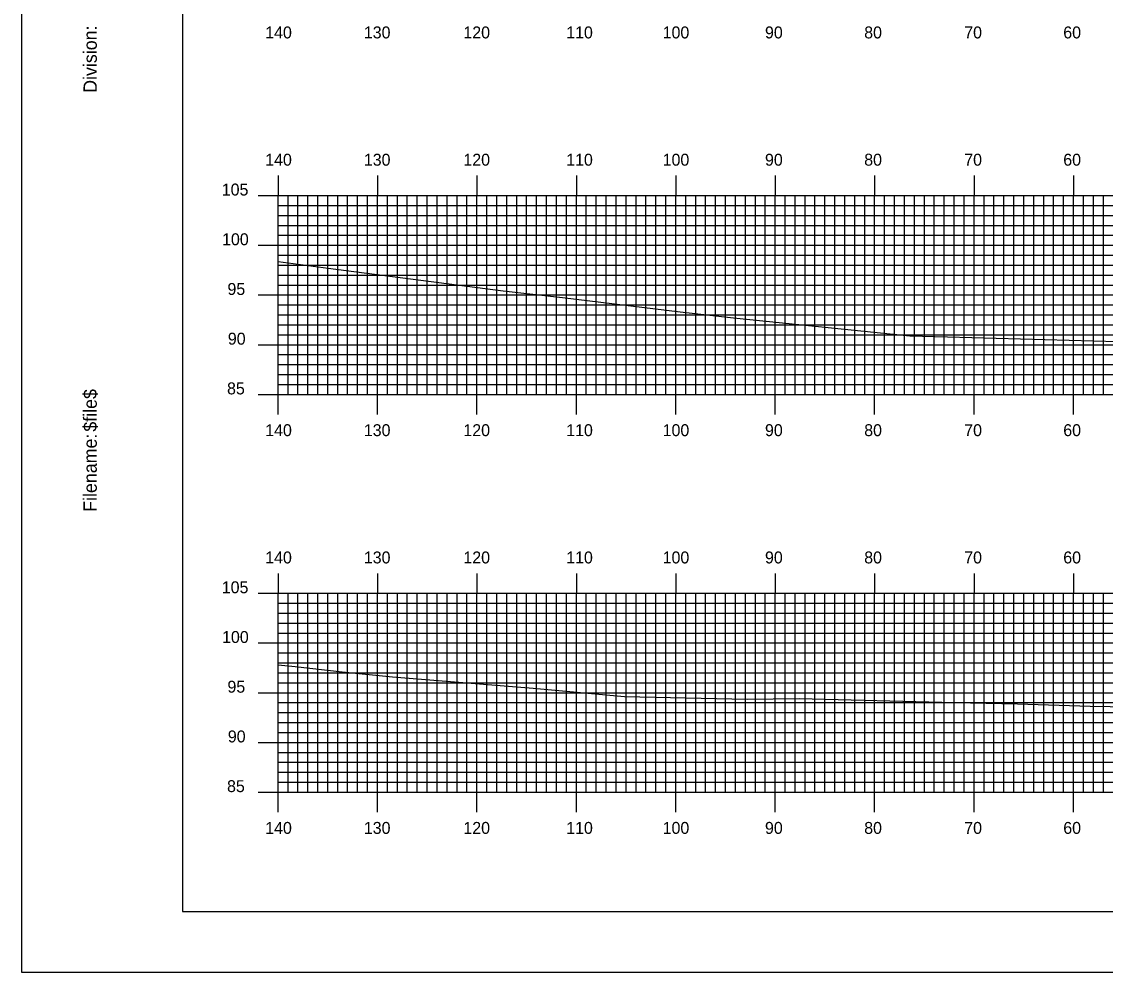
# Model space of a CAD drawing. Extents: x 1775564 to 1775907, y 442591 to 442811.
# Drawn here: x 1775563.9 to 1775672.9, y 442590.5 to 442686.2 of the extents above; entities that cross this region are included whole.
import ezdxf

# ---------------------------------------------------------------- set-up
doc = ezdxf.new("R2010")
doc.units = 0
for name, color, linetype in [('BORDER', 7, 'Continuous'), ('H_V ANNOTATION', 7, 'Continuous'), ('MAJOR', 7, 'Continuous'), ('MINOR', 7, 'Continuous'), ('PLOT BOUNDARY', 7, 'Continuous'), ('S_Roadway_Centerline', 7, 'Continuous')]:
    doc.layers.add(name, color=color, linetype=linetype)

msp = doc.modelspace()

# ---------------------------------------------------------------- linework, layer by layer
at = {"layer": 'BORDER'}
msp.add_lwpolyline([(1775580.11, 442596.67), (1775900.11, 442596.67), (1775900.11, 442806.67), (1775580.11, 442806.67)], close=True, dxfattribs=at)
at = {"layer": 'MAJOR'}
for p, q in [((1775589.71, 442670.67), (1775589.71, 442668.67)), ((1775599.71, 442670.67), (1775599.71, 442668.67)), ((1775609.71, 442670.67), (1775609.71, 442668.67)), ((1775619.71, 442670.67), (1775619.71, 442668.67)), ((1775629.71, 442670.67), (1775629.71, 442668.67)), ((1775639.71, 442670.67), (1775639.71, 442668.67)), ((1775649.71, 442670.67), (1775649.71, 442668.67)), ((1775659.71, 442670.67), (1775659.71, 442668.67)), ((1775669.71, 442670.67), (1775669.71, 442668.67)), ((1775587.71, 442668.67), (1775589.71, 442668.67)), ((1775589.71, 442668.67), (1775869.71, 442668.67)), ((1775589.71, 442648.67), (1775589.71, 442668.67)), ((1775589.71, 442648.67), (1775589.71, 442668.67)), ((1775589.71, 442668.67), (1775869.71, 442668.67)), ((1775599.71, 442648.67), (1775599.71, 442668.67)), ((1775609.71, 442648.67), (1775609.71, 442668.67)), ((1775619.71, 442648.67), (1775619.71, 442668.67)), ((1775629.71, 442648.67), (1775629.71, 442668.67)), ((1775639.71, 442648.67), (1775639.71, 442668.67)), ((1775649.71, 442648.67), (1775649.71, 442668.67)), ((1775659.71, 442648.67), (1775659.71, 442668.67)), ((1775669.71, 442648.67), (1775669.71, 442668.67)), ((1775587.71, 442663.67), (1775589.71, 442663.67)), ((1775589.71, 442663.67), (1775869.71, 442663.67)), ((1775587.71, 442658.67), (1775589.71, 442658.67)), ((1775589.71, 442658.67), (1775869.71, 442658.67)), ((1775587.71, 442653.67), (1775589.71, 442653.67)), ((1775589.71, 442653.67), (1775869.71, 442653.67)), ((1775587.71, 442648.67), (1775589.71, 442648.67)), ((1775589.71, 442648.67), (1775869.71, 442648.67)), ((1775589.71, 442648.67), (1775869.71, 442648.67)), ((1775589.71, 442646.66), (1775589.71, 442648.67)), ((1775599.71, 442646.66), (1775599.71, 442648.67)), ((1775609.71, 442646.66), (1775609.71, 442648.67)), ((1775619.71, 442646.66), (1775619.71, 442648.67)), ((1775629.71, 442646.66), (1775629.71, 442648.67)), ((1775639.71, 442646.66), (1775639.71, 442648.67)), ((1775649.71, 442646.66), (1775649.71, 442648.67)), ((1775659.71, 442646.66), (1775659.71, 442648.67)), ((1775669.71, 442646.66), (1775669.71, 442648.67)), ((1775589.71, 442630.67), (1775589.71, 442628.67)), ((1775599.71, 442630.67), (1775599.71, 442628.67)), ((1775609.71, 442630.67), (1775609.71, 442628.67)), ((1775619.71, 442630.67), (1775619.71, 442628.67)), ((1775629.71, 442630.67), (1775629.71, 442628.67)), ((1775639.71, 442630.67), (1775639.71, 442628.67)), ((1775649.71, 442630.67), (1775649.71, 442628.67)), ((1775659.71, 442630.67), (1775659.71, 442628.67)), ((1775669.71, 442630.67), (1775669.71, 442628.67)), ((1775587.71, 442628.67), (1775589.71, 442628.67)), ((1775589.71, 442628.67), (1775869.71, 442628.67)), ((1775589.71, 442608.67), (1775589.71, 442628.67)), ((1775589.71, 442608.67), (1775589.71, 442628.67)), ((1775589.71, 442628.67), (1775869.71, 442628.67)), ((1775599.71, 442608.67), (1775599.71, 442628.67)), ((1775609.71, 442608.67), (1775609.71, 442628.67)), ((1775619.71, 442608.67), (1775619.71, 442628.67)), ((1775629.71, 442608.67), (1775629.71, 442628.67)), ((1775639.71, 442608.67), (1775639.71, 442628.67)), ((1775649.71, 442608.67), (1775649.71, 442628.67)), ((1775659.71, 442608.67), (1775659.71, 442628.67)), ((1775669.71, 442608.67), (1775669.71, 442628.67)), ((1775587.71, 442623.67), (1775589.71, 442623.67)), ((1775589.71, 442623.67), (1775869.71, 442623.67)), ((1775587.71, 442618.67), (1775589.71, 442618.67)), ((1775589.71, 442618.67), (1775869.71, 442618.67)), ((1775587.71, 442613.67), (1775589.71, 442613.67)), ((1775589.71, 442613.67), (1775869.71, 442613.67)), ((1775587.71, 442608.67), (1775589.71, 442608.67)), ((1775589.71, 442608.67), (1775869.71, 442608.67)), ((1775589.71, 442608.67), (1775869.71, 442608.67)), ((1775589.71, 442606.66), (1775589.71, 442608.67)), ((1775599.71, 442606.66), (1775599.71, 442608.67)), ((1775609.71, 442606.66), (1775609.71, 442608.67)), ((1775619.71, 442606.66), (1775619.71, 442608.67)), ((1775629.71, 442606.66), (1775629.71, 442608.67)), ((1775639.71, 442606.66), (1775639.71, 442608.67)), ((1775649.71, 442606.66), (1775649.71, 442608.67)), ((1775659.71, 442606.66), (1775659.71, 442608.67)), ((1775669.71, 442606.66), (1775669.71, 442608.67))]:
    msp.add_line(p, q, dxfattribs=at)
at = {"layer": 'MINOR'}
for p, q in [((1775590.71, 442648.67), (1775590.71, 442668.67)), ((1775591.71, 442648.67), (1775591.71, 442668.67)), ((1775592.71, 442648.67), (1775592.71, 442668.67)), ((1775593.71, 442648.67), (1775593.71, 442668.67)), ((1775594.71, 442648.67), (1775594.71, 442668.67)), ((1775595.71, 442648.67), (1775595.71, 442668.67)), ((1775596.71, 442648.67), (1775596.71, 442668.67)), ((1775597.71, 442648.67), (1775597.71, 442668.67)), ((1775598.71, 442648.67), (1775598.71, 442668.67)), ((1775600.71, 442648.67), (1775600.71, 442668.67)), ((1775601.71, 442648.67), (1775601.71, 442668.67)), ((1775602.71, 442648.67), (1775602.71, 442668.67)), ((1775603.71, 442648.67), (1775603.71, 442668.67)), ((1775604.71, 442648.67), (1775604.71, 442668.67)), ((1775605.71, 442648.67), (1775605.71, 442668.67)), ((1775606.71, 442648.67), (1775606.71, 442668.67)), ((1775607.71, 442648.67), (1775607.71, 442668.67)), ((1775608.71, 442648.67), (1775608.71, 442668.67)), ((1775610.71, 442648.67), (1775610.71, 442668.67)), ((1775611.71, 442648.67), (1775611.71, 442668.67)), ((1775612.71, 442648.67), (1775612.71, 442668.67)), ((1775613.71, 442648.67), (1775613.71, 442668.67)), ((1775614.71, 442648.67), (1775614.71, 442668.67)), ((1775615.71, 442648.67), (1775615.71, 442668.67)), ((1775616.71, 442648.67), (1775616.71, 442668.67)), ((1775617.71, 442648.67), (1775617.71, 442668.67)), ((1775618.71, 442648.67), (1775618.71, 442668.67)), ((1775620.71, 442648.67), (1775620.71, 442668.67)), ((1775621.71, 442648.67), (1775621.71, 442668.67)), ((1775622.71, 442648.67), (1775622.71, 442668.67)), ((1775623.71, 442648.67), (1775623.71, 442668.67)), ((1775624.71, 442648.67), (1775624.71, 442668.67)), ((1775625.71, 442648.67), (1775625.71, 442668.67)), ((1775626.71, 442648.67), (1775626.71, 442668.67)), ((1775627.71, 442648.67), (1775627.71, 442668.67)), ((1775628.71, 442648.67), (1775628.71, 442668.67)), ((1775630.71, 442648.67), (1775630.71, 442668.67)), ((1775631.71, 442648.67), (1775631.71, 442668.67)), ((1775632.71, 442648.67), (1775632.71, 442668.67)), ((1775633.71, 442648.67), (1775633.71, 442668.67)), ((1775634.71, 442648.67), (1775634.71, 442668.67)), ((1775635.71, 442648.67), (1775635.71, 442668.67)), ((1775636.71, 442648.67), (1775636.71, 442668.67)), ((1775637.71, 442648.67), (1775637.71, 442668.67)), ((1775638.71, 442648.67), (1775638.71, 442668.67)), ((1775640.71, 442648.67), (1775640.71, 442668.67)), ((1775641.71, 442648.67), (1775641.71, 442668.67)), ((1775642.71, 442648.67), (1775642.71, 442668.67)), ((1775643.71, 442648.67), (1775643.71, 442668.67)), ((1775644.71, 442648.67), (1775644.71, 442668.67)), ((1775645.71, 442648.67), (1775645.71, 442668.67)), ((1775646.71, 442648.67), (1775646.71, 442668.67)), ((1775647.71, 442648.67), (1775647.71, 442668.67)), ((1775648.71, 442648.67), (1775648.71, 442668.67)), ((1775650.71, 442648.67), (1775650.71, 442668.67)), ((1775651.71, 442648.67), (1775651.71, 442668.67)), ((1775652.71, 442648.67), (1775652.71, 442668.67)), ((1775653.71, 442648.67), (1775653.71, 442668.67)), ((1775654.71, 442648.67), (1775654.71, 442668.67)), ((1775655.71, 442648.67), (1775655.71, 442668.67)), ((1775656.71, 442648.67), (1775656.71, 442668.67)), ((1775657.71, 442648.67), (1775657.71, 442668.67)), ((1775658.71, 442648.67), (1775658.71, 442668.67)), ((1775660.71, 442648.67), (1775660.71, 442668.67)), ((1775661.71, 442648.67), (1775661.71, 442668.67)), ((1775662.71, 442648.67), (1775662.71, 442668.67)), ((1775663.71, 442648.67), (1775663.71, 442668.67)), ((1775664.71, 442648.67), (1775664.71, 442668.67)), ((1775665.71, 442648.67), (1775665.71, 442668.67)), ((1775666.71, 442648.67), (1775666.71, 442668.67)), ((1775667.71, 442648.67), (1775667.71, 442668.67)), ((1775668.71, 442648.67), (1775668.71, 442668.67)), ((1775670.71, 442648.67), (1775670.71, 442668.67)), ((1775671.71, 442648.67), (1775671.71, 442668.67)), ((1775672.71, 442648.67), (1775672.71, 442668.67)), ((1775589.71, 442667.67), (1775869.71, 442667.67)), ((1775589.71, 442667.67), (1775591.72, 442667.67)), ((1775589.71, 442666.67), (1775869.71, 442666.67)), ((1775589.71, 442666.67), (1775591.72, 442666.67)), ((1775589.71, 442665.67), (1775869.71, 442665.67)), ((1775589.71, 442665.67), (1775591.72, 442665.67)), ((1775589.71, 442664.67), (1775869.71, 442664.67)), ((1775589.71, 442664.67), (1775591.72, 442664.67)), ((1775589.71, 442662.67), (1775869.71, 442662.67)), ((1775589.71, 442662.67), (1775591.72, 442662.67)), ((1775589.71, 442661.67), (1775869.71, 442661.67)), ((1775589.71, 442661.67), (1775591.72, 442661.67)), ((1775589.71, 442660.67), (1775869.71, 442660.67)), ((1775589.71, 442660.67), (1775591.72, 442660.67)), ((1775589.71, 442659.67), (1775869.71, 442659.67)), ((1775589.71, 442659.67), (1775591.72, 442659.67)), ((1775589.71, 442657.67), (1775869.71, 442657.67)), ((1775589.71, 442657.67), (1775591.72, 442657.67)), ((1775589.71, 442656.67), (1775869.71, 442656.67)), ((1775589.71, 442656.67), (1775591.72, 442656.67)), ((1775589.71, 442655.67), (1775869.71, 442655.67)), ((1775589.71, 442655.67), (1775591.72, 442655.67)), ((1775589.71, 442654.67), (1775869.71, 442654.67)), ((1775589.71, 442654.67), (1775591.72, 442654.67)), ((1775589.71, 442652.67), (1775869.71, 442652.67)), ((1775589.71, 442652.67), (1775591.72, 442652.67)), ((1775589.71, 442651.67), (1775869.71, 442651.67)), ((1775589.71, 442651.67), (1775591.72, 442651.67)), ((1775589.71, 442650.67), (1775869.71, 442650.67)), ((1775589.71, 442650.67), (1775591.72, 442650.67)), ((1775589.71, 442649.67), (1775869.71, 442649.67)), ((1775589.71, 442649.67), (1775591.72, 442649.67)), ((1775590.71, 442608.67), (1775590.71, 442628.67)), ((1775591.71, 442608.67), (1775591.71, 442628.67)), ((1775592.71, 442608.67), (1775592.71, 442628.67)), ((1775593.71, 442608.67), (1775593.71, 442628.67)), ((1775594.71, 442608.67), (1775594.71, 442628.67)), ((1775595.71, 442608.67), (1775595.71, 442628.67)), ((1775596.71, 442608.67), (1775596.71, 442628.67)), ((1775597.71, 442608.67), (1775597.71, 442628.67)), ((1775598.71, 442608.67), (1775598.71, 442628.67)), ((1775600.71, 442608.67), (1775600.71, 442628.67)), ((1775601.71, 442608.67), (1775601.71, 442628.67)), ((1775602.71, 442608.67), (1775602.71, 442628.67)), ((1775603.71, 442608.67), (1775603.71, 442628.67)), ((1775604.71, 442608.67), (1775604.71, 442628.67)), ((1775605.71, 442608.67), (1775605.71, 442628.67)), ((1775606.71, 442608.67), (1775606.71, 442628.67)), ((1775607.71, 442608.67), (1775607.71, 442628.67)), ((1775608.71, 442608.67), (1775608.71, 442628.67)), ((1775610.71, 442608.67), (1775610.71, 442628.67)), ((1775611.71, 442608.67), (1775611.71, 442628.67)), ((1775612.71, 442608.67), (1775612.71, 442628.67)), ((1775613.71, 442608.67), (1775613.71, 442628.67)), ((1775614.71, 442608.67), (1775614.71, 442628.67)), ((1775615.71, 442608.67), (1775615.71, 442628.67)), ((1775616.71, 442608.67), (1775616.71, 442628.67)), ((1775617.71, 442608.67), (1775617.71, 442628.67)), ((1775618.71, 442608.67), (1775618.71, 442628.67)), ((1775620.71, 442608.67), (1775620.71, 442628.67)), ((1775621.71, 442608.67), (1775621.71, 442628.67)), ((1775622.71, 442608.67), (1775622.71, 442628.67)), ((1775623.71, 442608.67), (1775623.71, 442628.67)), ((1775624.71, 442608.67), (1775624.71, 442628.67)), ((1775625.71, 442608.67), (1775625.71, 442628.67)), ((1775626.71, 442608.67), (1775626.71, 442628.67)), ((1775627.71, 442608.67), (1775627.71, 442628.67)), ((1775628.71, 442608.67), (1775628.71, 442628.67)), ((1775630.71, 442608.67), (1775630.71, 442628.67)), ((1775631.71, 442608.67), (1775631.71, 442628.67)), ((1775632.71, 442608.67), (1775632.71, 442628.67)), ((1775633.71, 442608.67), (1775633.71, 442628.67)), ((1775634.71, 442608.67), (1775634.71, 442628.67)), ((1775635.71, 442608.67), (1775635.71, 442628.67)), ((1775636.71, 442608.67), (1775636.71, 442628.67)), ((1775637.71, 442608.67), (1775637.71, 442628.67)), ((1775638.71, 442608.67), (1775638.71, 442628.67)), ((1775640.71, 442608.67), (1775640.71, 442628.67)), ((1775641.71, 442608.67), (1775641.71, 442628.67)), ((1775642.71, 442608.67), (1775642.71, 442628.67)), ((1775643.71, 442608.67), (1775643.71, 442628.67)), ((1775644.71, 442608.67), (1775644.71, 442628.67)), ((1775645.71, 442608.67), (1775645.71, 442628.67)), ((1775646.71, 442608.67), (1775646.71, 442628.67)), ((1775647.71, 442608.67), (1775647.71, 442628.67)), ((1775648.71, 442608.67), (1775648.71, 442628.67)), ((1775650.71, 442608.67), (1775650.71, 442628.67)), ((1775651.71, 442608.67), (1775651.71, 442628.67)), ((1775652.71, 442608.67), (1775652.71, 442628.67)), ((1775653.71, 442608.67), (1775653.71, 442628.67)), ((1775654.71, 442608.67), (1775654.71, 442628.67)), ((1775655.71, 442608.67), (1775655.71, 442628.67)), ((1775656.71, 442608.67), (1775656.71, 442628.67)), ((1775657.71, 442608.67), (1775657.71, 442628.67)), ((1775658.71, 442608.67), (1775658.71, 442628.67)), ((1775660.71, 442608.67), (1775660.71, 442628.67)), ((1775661.71, 442608.67), (1775661.71, 442628.67)), ((1775662.71, 442608.67), (1775662.71, 442628.67)), ((1775663.71, 442608.67), (1775663.71, 442628.67)), ((1775664.71, 442608.67), (1775664.71, 442628.67)), ((1775665.71, 442608.67), (1775665.71, 442628.67)), ((1775666.71, 442608.67), (1775666.71, 442628.67)), ((1775667.71, 442608.67), (1775667.71, 442628.67)), ((1775668.71, 442608.67), (1775668.71, 442628.67)), ((1775670.71, 442608.67), (1775670.71, 442628.67)), ((1775671.71, 442608.67), (1775671.71, 442628.67)), ((1775672.71, 442608.67), (1775672.71, 442628.67)), ((1775589.71, 442627.67), (1775869.71, 442627.67)), ((1775589.71, 442627.67), (1775591.72, 442627.67)), ((1775589.71, 442626.67), (1775869.71, 442626.67)), ((1775589.71, 442626.67), (1775591.72, 442626.67)), ((1775589.71, 442625.67), (1775869.71, 442625.67)), ((1775589.71, 442625.67), (1775591.72, 442625.67)), ((1775589.71, 442624.67), (1775869.71, 442624.67)), ((1775589.71, 442624.67), (1775591.72, 442624.67)), ((1775589.71, 442622.67), (1775869.71, 442622.67)), ((1775589.71, 442622.67), (1775591.72, 442622.67)), ((1775589.71, 442621.67), (1775869.71, 442621.67)), ((1775589.71, 442621.67), (1775591.72, 442621.67)), ((1775589.71, 442620.67), (1775869.71, 442620.67)), ((1775589.71, 442620.67), (1775591.72, 442620.67)), ((1775589.71, 442619.67), (1775869.71, 442619.67)), ((1775589.71, 442619.67), (1775591.72, 442619.67)), ((1775589.71, 442617.67), (1775869.71, 442617.67)), ((1775589.71, 442617.67), (1775591.72, 442617.67)), ((1775589.71, 442616.67), (1775869.71, 442616.67)), ((1775589.71, 442616.67), (1775591.72, 442616.67)), ((1775589.71, 442615.67), (1775869.71, 442615.67)), ((1775589.71, 442615.67), (1775591.72, 442615.67)), ((1775589.71, 442614.67), (1775869.71, 442614.67)), ((1775589.71, 442614.67), (1775591.72, 442614.67)), ((1775589.71, 442612.67), (1775869.71, 442612.67)), ((1775589.71, 442612.67), (1775591.72, 442612.67)), ((1775589.71, 442611.67), (1775869.71, 442611.67)), ((1775589.71, 442611.67), (1775591.72, 442611.67)), ((1775589.71, 442610.67), (1775869.71, 442610.67)), ((1775589.71, 442610.67), (1775591.72, 442610.67)), ((1775589.71, 442609.67), (1775869.71, 442609.67)), ((1775589.71, 442609.67), (1775591.72, 442609.67))]:
    msp.add_line(p, q, dxfattribs=at)
at = {"layer": 'PLOT BOUNDARY'}
msp.add_lwpolyline([(1775563.92, 442590.55), (1775903.92, 442590.55), (1775903.92, 442810.55), (1775563.92, 442810.55)], close=True, dxfattribs=at)
at = {"layer": 'S_Roadway_Centerline'}
for points in [[(1775589.71, 442662.04), (1775594.76, 442661.38), (1775612.35, 442659.1), (1775618.32, 442658.42), (1775630.14, 442656.98), (1775635.5, 442656.38), (1775653.24, 442654.55), (1775657.03, 442654.45), (1775676.6, 442653.91), (1775679.69, 442653.89), (1775690.11, 442653.74), (1775702.35, 442654.21), (1775712.87, 442654.41), (1775724.16, 442654.22), (1775746.74, 442653.75), (1775747.04, 442653.75), (1775747.18, 442653.75), (1775747.31, 442653.75), (1775762.01, 442654.4), (1775778.33, 442655.34), (1775791.99, 442656.2)], [(1775589.71, 442621.46), (1775591.43, 442621.29), (1775596.15, 442620.77), (1775601.23, 442620.26), (1775615.38, 442619.14), (1775624.54, 442618.3), (1775636.88, 442618.03), (1775642.13, 442618.09), (1775657.78, 442617.68), (1775664.09, 442617.55), (1775671.37, 442617.31), (1775677.37, 442617.23)]]:
    msp.add_lwpolyline(points, dxfattribs=at)

# ---------------------------------------------------------------- texts
at = {"layer": 'BORDER'}
for s, p in [('Division:', (1775571.48, 442679)), ('$file$', (1775571.48, 442644.92)), ('Filename:', (1775571.48, 442636.86))]:
    msp.add_text(s, height=1.339, rotation=90, dxfattribs=at).set_placement(p)
at = {"layer": 'H_V ANNOTATION'}
for s, p in [('140', (1775588.42, 442684.47)), ('130', (1775598.34, 442684.47)), ('120', (1775608.35, 442684.47)), ('110', (1775618.69, 442684.47)), ('100', (1775628.39, 442684.47)), ('90', (1775638.68, 442684.47)), ('80', (1775648.66, 442684.47)), ('70', (1775658.72, 442684.47)), ('60', (1775668.68, 442684.47)), ('140', (1775588.42, 442671.67)), ('130', (1775598.34, 442671.67)), ('120', (1775608.35, 442671.67)), ('110', (1775618.69, 442671.67)), ('100', (1775628.39, 442671.67)), ('90', (1775638.68, 442671.67)), ('80', (1775648.66, 442671.67)), ('70', (1775658.72, 442671.67)), ('60', (1775668.68, 442671.67)), ('105', (1775584.05, 442668.67)), ('100', (1775584.08, 442663.67)), ('95', (1775584.62, 442658.67)), ('90', (1775584.66, 442653.67)), ('85', (1775584.58, 442648.67)), ('140', (1775588.42, 442644.47)), ('130', (1775598.34, 442644.47)), ('120', (1775608.35, 442644.47)), ('110', (1775618.69, 442644.47)), ('100', (1775628.39, 442644.47)), ('90', (1775638.68, 442644.47)), ('80', (1775648.66, 442644.47)), ('70', (1775658.72, 442644.47)), ('60', (1775668.68, 442644.47)), ('140', (1775588.42, 442631.67)), ('130', (1775598.34, 442631.67)), ('120', (1775608.35, 442631.67)), ('110', (1775618.69, 442631.67)), ('100', (1775628.39, 442631.67)), ('90', (1775638.68, 442631.67)), ('80', (1775648.66, 442631.67)), ('70', (1775658.72, 442631.67)), ('60', (1775668.68, 442631.67)), ('105', (1775584.05, 442628.67)), ('100', (1775584.08, 442623.67)), ('95', (1775584.62, 442618.67)), ('90', (1775584.66, 442613.67)), ('85', (1775584.58, 442608.67)), ('140', (1775588.42, 442604.47)), ('130', (1775598.34, 442604.47)), ('120', (1775608.35, 442604.47)), ('110', (1775618.69, 442604.47)), ('100', (1775628.39, 442604.47)), ('90', (1775638.68, 442604.47)), ('80', (1775648.66, 442604.47)), ('70', (1775658.72, 442604.47)), ('60', (1775668.68, 442604.47))]:
    msp.add_text(s, height=1.2, dxfattribs=at).set_placement(p)
at = {"layer": 'MAJOR'}
for p in [(1775589.7, 442648.67), (1775589.7, 442608.67)]:
    msp.add_text('-', height=0.012, dxfattribs=at).set_placement(p)

doc.saveas('drawing.dxf')
